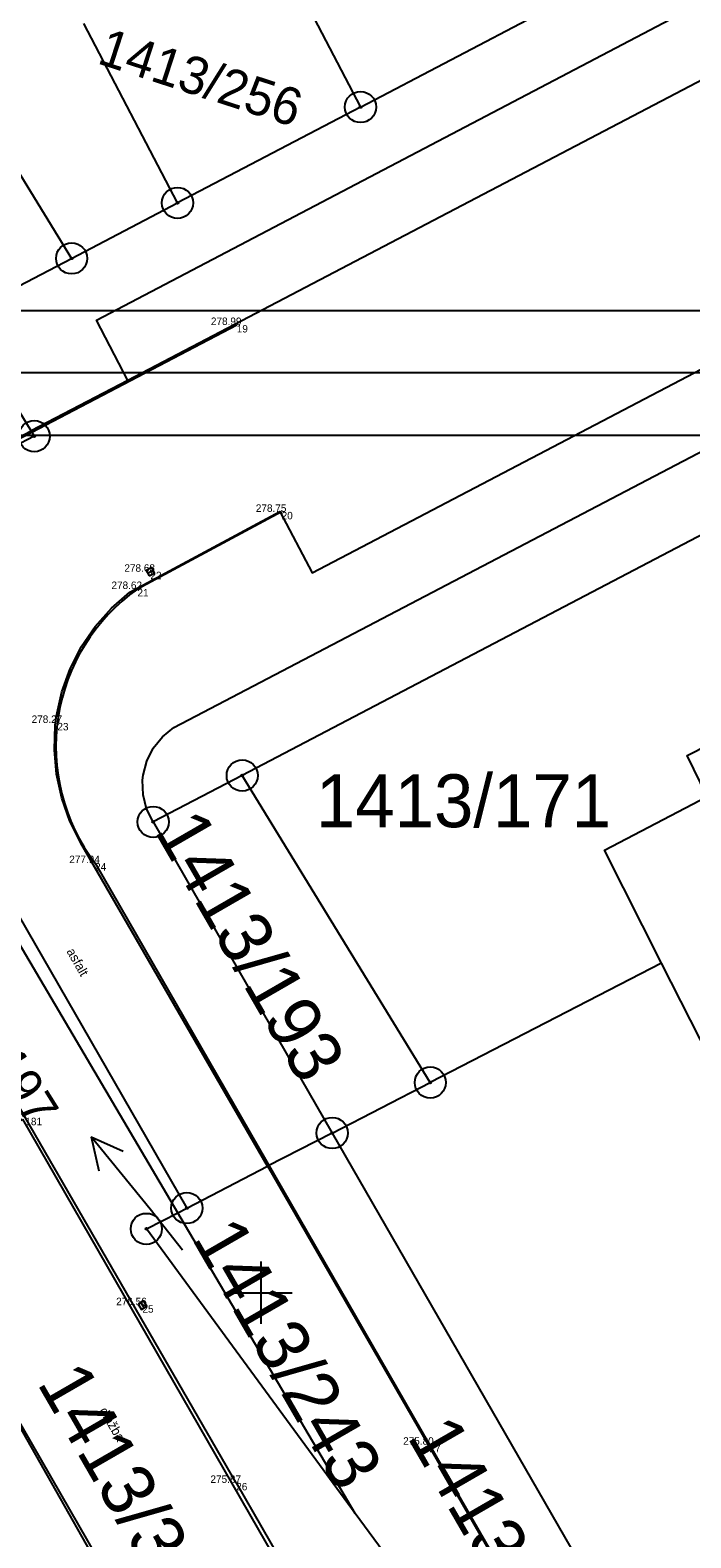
# Model space of a CAD drawing. Extents: x -771260 to -770828, y -1053564 to -1052811.
# Drawn here: x -770957.41 to -770936.19, y -1053157.87 to -1053109.45 of the extents above; entities that cross this region are included whole.
import ezdxf

# ---------------------------------------------------------------- set-up
doc = ezdxf.new("R2010")
doc.units = 0
for name, color, linetype in [('14_8_2023_krizky', 7, 'Continuous'), ('18_8_2023_ram_gs', 7, 'Continuous'), ('18_8_2023_vypln_ramu', 7, 'Continuous'), ('25_10_2019_asfalt', 7, 'Continuous'), ('25_10_2019_dlazba', 7, 'Continuous'), ('25_10_2019_popis_povrchu', 7, 'Continuous'), ('25_10_2019_vpust', 7, 'Continuous'), ('25_10_2019_zamereny_bod', 7, 'Continuous'), ('25_10_2019_zamereny_bod_cislo', 7, 'Continuous'), ('25_10_2019_zamereny_bod_vyska', 7, 'Continuous'), ('25_3_2019_krizky_JTSK', 7, 'Continuous'), ('Default', 7, 'Continuous'), ('DKM_Hranice parcel', 7, 'Continuous'), ('DKM_Parcelní čísla', 7, 'Continuous'), ('DKM_Pop  PČ popisy', 7, 'Continuous'), ('DKM_Značky bodu BP', 7, 'Continuous')]:
    doc.layers.add(name, color=color, linetype=linetype)

# ---------------------------------------------------------------- blocks, each defined once
blk = doc.blocks.new('6.301')
at = {"layer": '25_10_2019_vpust'}
blk.add_line((-5, 0), (5, 0), dxfattribs=at)
blk.add_lwpolyline([(-5, -5), (5, -5), (5, 5), (-5, 5)], close=True, dxfattribs=at)
blk = doc.blocks.new('POINT_DISPLAY')
at = {"layer": 'Default'}
blk.add_line((0, 0), (0, 0), dxfattribs=at)
blk = doc.blocks.new('KRIZEK')
at = {"layer": '25_3_2019_krizky_JTSK'}
for p, q in [((0, 10), (0, -10)), ((-10, 0), (10, 0))]:
    blk.add_line(p, q, dxfattribs=at)

msp = doc.modelspace()

# ---------------------------------------------------------------- linework, layer by layer
at = {"layer": '18_8_2023_ram_gs'}
for points in [[(-770830.522, -1053118.46), (-771040.522, -1053118.46), (-771040.522, -1053415.46), (-770830.522, -1053415.46)], [(-770832.522, -1053120.46), (-771038.522, -1053120.46), (-771038.522, -1053413.46), (-770832.522, -1053413.46)]]:
    msp.add_lwpolyline(points, close=True, dxfattribs=at)
at = {"layer": '18_8_2023_vypln_ramu'}
msp.add_lwpolyline([(-771040.522, -1053415.46), (-771036.522, -1053411.46), (-771036.522, -1053122.46), (-770834.522, -1053122.46), (-770830.522, -1053118.46), (-771040.522, -1053118.46)], close=True, dxfattribs=at)
at = {"layer": '25_10_2019_asfalt'}
for p, q in [((-770965.578, -1053126.659), (-770950.776, -1053118.92)), ((-770949.335, -1053124.921), (-770953.965, -1053127.399)), ((-770955.326, -1053136.203), (-770944.586, -1053154.881)), ((-770944.586, -1053154.881), (-770936.518, -1053168.87)), ((-770950.794, -1053156.108), (-770947.365, -1053162.068))]:
    msp.add_line(p, q, dxfattribs=at)
msp.add_lwpolyline([(-770950.794, -1053156.108), (-770957.566, -1053144.381), (-770961.698, -1053137.299)], dxfattribs=at)
msp.add_arc((-770950.384, -1053132.46), 6.199, 125.2803, 217.1442, dxfattribs=at)
at = {"layer": '25_10_2019_dlazba'}
msp.add_line((-770961.93, -1053146.911), (-770951.758, -1053164.599), dxfattribs=at)
at = {"layer": 'DKM_Hranice parcel'}
for p, q in [((-770835.31, -1053058.4), (-770954.27, -1053120.7)), ((-770949.82, -1053106.16), (-770946.8, -1053111.92)), ((-770952.68, -1053115), (-770955.69, -1053109.24)), ((-770946.8, -1053111.92), (-770941, -1053108.88)), ((-770946.8, -1053111.92), (-770952.68, -1053115)), ((-770956.08, -1053116.78), (-770952.68, -1053115)), ((-770959.63, -1053118.64), (-770956.08, -1053116.78)), ((-770922.03, -1053118.42), (-770950.6, -1053133.39)), ((-770957.38, -1053122.32), (-770959.63, -1053118.64)), ((-770954.27, -1053120.7), (-770957.38, -1053122.32)), ((-770950.6, -1053133.39), (-770953.46, -1053134.88)), ((-770944.56, -1053143.25), (-770950.6, -1053133.39)), ((-770953.46, -1053134.88), (-770947.71, -1053144.87)), ((-770949.79, -1053145.94), (-770955.78, -1053135.56)), ((-770937.13, -1053139.42), (-770944.56, -1053143.25)), ((-770947.71, -1053144.87), (-770944.56, -1053143.25)), ((-770957.66, -1053144.43), (-770947.48, -1053162.13)), ((-770947.71, -1053144.87), (-770949.79, -1053145.94)), ((-770947.71, -1053144.87), (-770936.97, -1053163.54)), ((-770952.38, -1053147.28), (-770949.79, -1053145.94)), ((-770949.79, -1053145.94), (-770932.91, -1053175.2)), ((-770952.67, -1053147.43), (-770952.38, -1053147.28)), ((-770946.97, -1053157.09), (-770952.67, -1053147.43)), ((-770945.92, -1053158.51), (-770946.97, -1053157.09))]:
    msp.add_line(p, q, dxfattribs=at)
for points in [[(-770954.27, -1053120.7), (-770955.28, -1053118.76), (-770836.38, -1053056.41), (-770835.31, -1053058.4)], [(-770954.21, -1053127.5), (-770949.39, -1053124.91), (-770948.35, -1053126.88), (-770834.522, -1053067.272)], [(-770952.8, -1053131.85), (-770951.85, -1053131.35), (-770834.522, -1053069.944)], [(-770974.67, -1053076.44), (-770976.66, -1053083.17), (-770956.08, -1053116.78)], [(-770937.13, -1053139.42), (-770938.97, -1053135.79), (-770935.67, -1053134.06), (-770936.31, -1053132.75), (-770932.03, -1053130.57), (-770926.49, -1053127.73), (-770928.19, -1053124.27), (-770922.47, -1053121.39), (-770919.94, -1053126.43), (-770925.65, -1053129.3), (-770927.71, -1053130.36), (-770926.02, -1053133.69)], [(-770952.67, -1053147.43), (-770965.1, -1053126.35), (-770957.38, -1053122.32)], [(-770957.38, -1053122.32), (-770957.28, -1053122.49), (-770964.48, -1053126.26), (-770952.38, -1053147.28)], [(-770955.78, -1053135.56), (-770956.135, -1053134.858), (-770956.399, -1053134.116), (-770956.566, -1053133.346), (-770956.634, -1053132.562), (-770956.603, -1053131.776), (-770956.563, -1053131.467), (-770956.393, -1053130.699), (-770956.127, -1053129.958), (-770955.77, -1053129.256), (-770955.326, -1053128.606), (-770954.803, -1053128.017), (-770954.21, -1053127.5)], [(-770953.46, -1053134.88), (-770953.67, -1053134.462), (-770953.786, -1053134.009), (-770953.804, -1053133.541), (-770953.786, -1053133.378), (-770953.669, -1053132.925), (-770953.459, -1053132.507), (-770953.165, -1053132.143), (-770952.8, -1053131.85)], [(-770926.02, -1053133.69), (-770924.44, -1053136.81), (-770925.42, -1053137.31), (-770923.95, -1053140.19), (-770931.94, -1053144.28), (-770933.42, -1053141.37), (-770935.58, -1053142.47), (-770937.13, -1053139.42)], [(-770951.76, -1053164.59), (-770951.89, -1053164.66), (-770961.93, -1053146.91), (-770957.66, -1053144.43)], [(-770946.97, -1053157.09), (-770953.68, -1053147.95), (-770952.67, -1053147.43)]]:
    msp.add_lwpolyline(points, dxfattribs=at)
at = {"layer": 'DKM_Pop  PČ popisy'}
for p, q in [((-770953.56, -1053147.32), (-770955.449, -1053144.988)), ((-770955.449, -1053144.988), (-770954.429, -1053145.451)), ((-770955.449, -1053144.988), (-770955.207, -1053146.081)), ((-770952.52, -1053148.63), (-770953.56, -1053147.32))]:
    msp.add_line(p, q, dxfattribs=at)
at = {"layer": 'DKM_Značky bodu BP'}
for centre, radius in [((-770946.8, -1053111.92), 0.5), ((-770946.8, -1053111.92), 0.0303), ((-770952.68, -1053115), 0.5), ((-770952.68, -1053115), 0.0303), ((-770956.08, -1053116.78), 0.5), ((-770956.08, -1053116.78), 0.0303), ((-770957.28, -1053122.49), 0.5), ((-770957.28, -1053122.49), 0.0303), ((-770950.6, -1053133.39), 0.5), ((-770950.6, -1053133.39), 0.0303), ((-770953.46, -1053134.88), 0.5), ((-770953.46, -1053134.88), 0.0303), ((-770944.56, -1053143.25), 0.5), ((-770944.56, -1053143.25), 0.0303), ((-770947.71, -1053144.87), 0.5), ((-770947.71, -1053144.87), 0.0303), ((-770952.38, -1053147.28), 0.5), ((-770953.68, -1053147.95), 0.5), ((-770952.38, -1053147.28), 0.0303), ((-770953.68, -1053147.95), 0.0303)]:
    msp.add_circle(centre, radius, dxfattribs=at)

# ---------------------------------------------------------------- block references
at = {"layer": '14_8_2023_krizky', "xscale": 0.1, "yscale": 0.10000000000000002}
msp.add_blockref('KRIZEK', (-770950, -1053150), dxfattribs=at)
at = {"layer": '25_10_2019_vpust', "yscale": 0.020000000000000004}
for p, xscale, rotation in [((-770953.55, -1053126.845), 0.020000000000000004, 27.629246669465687), ((-770953.804, -1053150.4), 0.02, -56.95064726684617)]:
    msp.add_blockref('6.301', p, dxfattribs=dict(at, xscale=xscale, rotation=rotation))
at = {"layer": '25_10_2019_zamereny_bod', "xscale": 0.1, "yscale": 0.10000000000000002}
for p in [(-770950.776, -1053118.92), (-770949.335, -1053124.921), (-770953.55, -1053126.845), (-770953.965, -1053127.399), (-770956.537, -1053131.7), (-770955.326, -1053136.203), (-770953.804, -1053150.4), (-770944.586, -1053154.881), (-770950.794, -1053156.108)]:
    msp.add_blockref('POINT_DISPLAY', p, dxfattribs=at)

# ---------------------------------------------------------------- texts
at = {"layer": '25_10_2019_popis_povrchu'}
for s, rotation, p in [('asfalt', 299.5537, (-770956.252, -1053139.035)), ('dlažba', 300.687, (-770955.206, -1053153.79))]:
    msp.add_text(s, height=0.3, rotation=rotation, dxfattribs=at).set_placement(p)
at = {"layer": '25_10_2019_zamereny_bod_cislo'}
for s, p in [('19', (-770950.776, -1053119.16)), ('20', (-770949.335, -1053125.161)), ('22', (-770953.55, -1053127.085)), ('21', (-770953.965, -1053127.639)), ('23', (-770956.537, -1053131.94)), ('24', (-770955.326, -1053136.443)), ('181', (-770957.566, -1053144.621)), ('25', (-770953.804, -1053150.64)), ('27', (-770944.586, -1053155.121)), ('26', (-770950.794, -1053156.348))]:
    msp.add_text(s, height=0.24, dxfattribs=at).set_placement(p)
at = {"layer": '25_10_2019_zamereny_bod_vyska'}
for s, p in [('278.99 ', (-770951.606, -1053118.92)), ('278.75 ', (-770950.163, -1053124.921)), ('278.68 ', (-770954.385, -1053126.845)), ('278.62 ', (-770954.8, -1053127.399)), ('278.27 ', (-770957.364, -1053131.7)), ('277.94 ', (-770956.155, -1053136.203)), ('276.56 ', (-770954.649, -1053150.4)), ('275.80 ', (-770945.432, -1053154.881)), ('275.87 ', (-770951.621, -1053156.108))]:
    msp.add_text(s, height=0.24, dxfattribs=at).set_placement(p)
at = {"layer": 'DKM_Parcelní čísla'}
for s, height, rotation, p in [('1413/256', 1.2, 342, (-770955.297, -1053110.506)), ('1413/193', 1.7, 300, (-770953.439, -1053135.161)), ('1413/197', 1.139, 302, (-770960.775, -1053139.351)), ('1413/243', 1.7, 300, (-770952.236, -1053148.255)), ('1413/360', 1.7, 300, (-770957.209, -1053152.901)), ('1413/192', 1.7, 300, (-770945.319, -1053154.621))]:
    msp.add_text(s, height=height, rotation=rotation, dxfattribs=at).set_placement(p)
msp.add_text('1413/171', height=1.7, dxfattribs=at).set_placement((-770948.235, -1053135.05))

doc.saveas('drawing.dxf')
